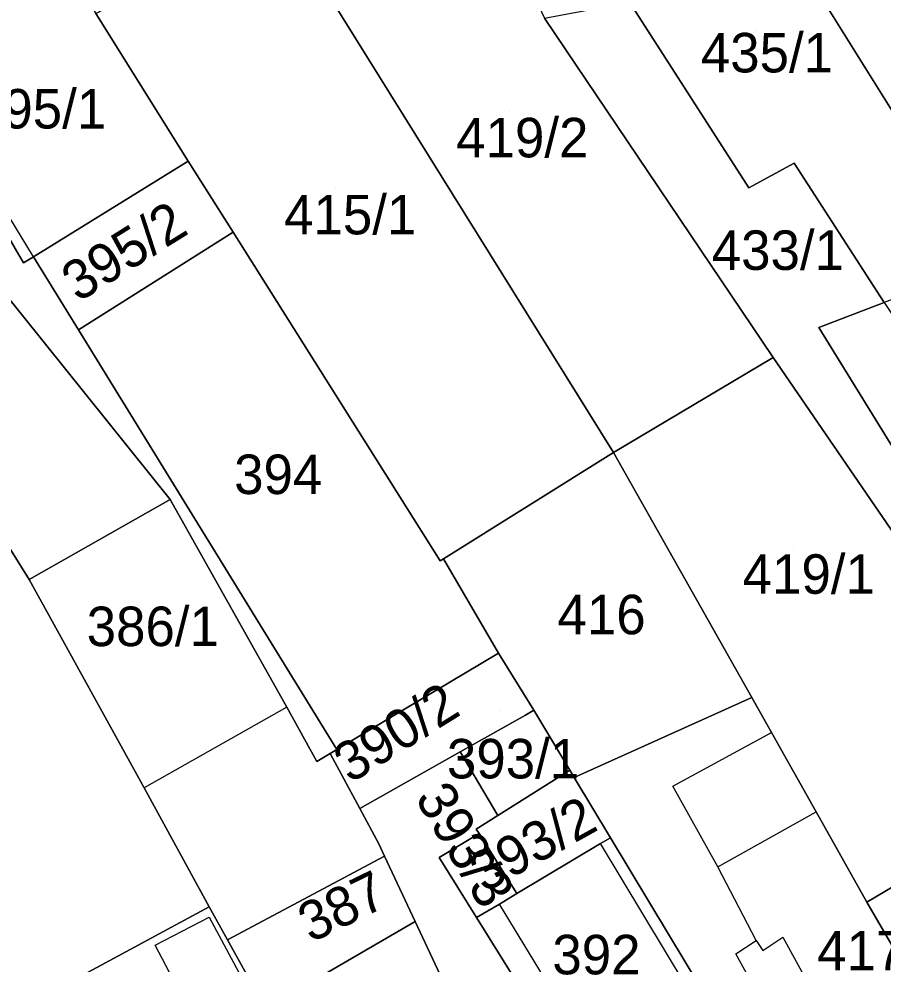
# Model space of a CAD drawing. Extents: x -263943 to -261149, y -1236934 to -1230686.
# Drawn here: x -262790.27 to -262746.54, y -1235631.56 to -1235583.7 of the extents above; entities that cross this region are included whole.
import ezdxf

# ---------------------------------------------------------------- set-up
doc = ezdxf.new("R2010")
doc.units = 0
for name, color, linetype in [('body_kn', 7, 'Continuous'), ('kladpar_druhypozemkov', 7, 'Continuous'), ('kladpar_hranice', 7, 'Continuous'), ('kladpar_parcelnecisla', 7, 'Continuous'), ('kladpar_plochy', 7, 'Continuous'), ('zappar_hrandruhpozemk', 7, 'Continuous')]:
    doc.layers.add(name, color=color, linetype=linetype)

msp = doc.modelspace()

# ---------------------------------------------------------------- linework, layer by layer
at = {"layer": 'body_kn'}
for p, q in [((-262781.7, -1235590.9), (-262781.7, -1235590.9)), ((-262781.7, -1235590.9), (-262781.7, -1235590.9)), ((-262751.05, -1235591), (-262751.05, -1235591)), ((-262753.34, -1235592.26), (-262753.34, -1235592.26)), ((-262779.43, -1235594.5), (-262779.43, -1235594.5)), ((-262790.04, -1235596.05), (-262790.04, -1235596.05)), ((-262789.53, -1235595.74), (-262789.53, -1235595.74)), ((-262789.53, -1235595.74), (-262789.53, -1235595.74)), ((-262787.25, -1235599.45), (-262787.25, -1235599.45)), ((-262749.8, -1235599.32), (-262749.8, -1235599.32)), ((-262749.8, -1235599.32), (-262749.8, -1235599.32)), ((-262752.1, -1235600.84), (-262752.1, -1235600.84)), ((-262760.19, -1235605.65), (-262760.19, -1235605.65)), ((-262782.61, -1235608.04), (-262782.61, -1235608.04)), ((-262768.95, -1235611.14), (-262768.95, -1235611.14)), ((-262768.95, -1235611.14), (-262768.95, -1235611.14)), ((-262768.79, -1235611.04), (-262768.79, -1235611.04)), ((-262789.76, -1235612.09), (-262789.76, -1235612.09)), ((-262766, -1235615.81), (-262766, -1235615.81)), ((-262753.18, -1235618.06), (-262753.18, -1235618.06)), ((-262776.72, -1235618.56), (-262776.72, -1235618.56)), ((-262776.72, -1235618.56), (-262776.72, -1235618.56)), ((-262764.64, -1235618.95), (-262764.64, -1235618.95)), ((-262764.22, -1235618.71), (-262764.22, -1235618.71)), ((-262764.22, -1235618.71), (-262764.22, -1235618.71)), ((-262752.19, -1235619.83), (-262752.19, -1235619.83)), ((-262774.53, -1235620.9), (-262774.53, -1235620.9)), ((-262774.53, -1235620.9), (-262774.53, -1235620.9)), ((-262774.19, -1235620.7), (-262774.19, -1235620.7)), ((-262774.19, -1235620.7), (-262774.19, -1235620.7)), ((-262767.95, -1235620.82), (-262767.95, -1235620.82)), ((-262767.95, -1235620.82), (-262767.95, -1235620.82)), ((-262775.19, -1235621.3), (-262775.19, -1235621.3)), ((-262762.4, -1235621.74), (-262762.4, -1235621.74)), ((-262762.17, -1235622.12), (-262762.17, -1235622.12)), ((-262783.94, -1235622.63), (-262783.94, -1235622.63)), ((-262757.19, -1235622.55), (-262757.19, -1235622.55)), ((-262773.02, -1235623.69), (-262773.02, -1235623.69)), ((-262749.93, -1235623.85), (-262749.93, -1235623.85)), ((-262766.03, -1235624.03), (-262766.03, -1235624.03)), ((-262766.03, -1235624.03), (-262766.03, -1235624.03)), ((-262767.14, -1235624.73), (-262767.14, -1235624.73)), ((-262766.99, -1235624.95), (-262766.99, -1235624.95)), ((-262760.34, -1235625.16), (-262760.34, -1235625.16)), ((-262772.06, -1235625.47), (-262772.06, -1235625.47)), ((-262767.82, -1235625.45), (-262767.82, -1235625.45)), ((-262760.84, -1235625.46), (-262760.84, -1235625.46)), ((-262771.77, -1235626.1), (-262771.77, -1235626.1)), ((-262769, -1235626.16), (-262769, -1235626.16)), ((-262754.91, -1235626.63), (-262754.91, -1235626.63)), ((-262765.07, -1235627.99), (-262765.07, -1235627.99)), ((-262765.07, -1235627.99), (-262765.07, -1235627.99)), ((-262765.95, -1235628.52), (-262765.95, -1235628.52)), ((-262747.36, -1235628.43), (-262747.36, -1235628.43)), ((-262747.36, -1235628.43), (-262747.36, -1235628.43)), ((-262780.64, -1235628.67), (-262780.64, -1235628.67)), ((-262780.64, -1235628.67), (-262780.64, -1235628.67)), ((-262780.65, -1235629.18), (-262780.65, -1235629.18)), ((-262770.22, -1235629.41), (-262770.22, -1235629.41)), ((-262767.11, -1235629.21), (-262767.11, -1235629.21)), ((-262779.72, -1235630.33), (-262779.72, -1235630.33)), ((-262779.72, -1235630.33), (-262779.72, -1235630.33)), ((-262752.97, -1235630.37), (-262752.97, -1235630.37)), ((-262752.97, -1235630.37), (-262752.97, -1235630.37)), ((-262751.61, -1235630.2), (-262751.61, -1235630.2)), ((-262783.37, -1235630.61), (-262783.37, -1235630.61)), ((-262783.37, -1235630.61), (-262783.37, -1235630.61)), ((-262753.99, -1235631.04), (-262753.99, -1235631.04)), ((-262752.63, -1235630.88), (-262752.63, -1235630.88))]:
    msp.add_line(p, q, dxfattribs=at)
at = {"layer": 'kladpar_druhypozemkov'}
for p, q in [((-262752.93, -1235584.31), (-262752.93, -1235584.31)), ((-262789.23, -1235587.18), (-262789.23, -1235587.18)), ((-262765.43, -1235588.41), (-262765.43, -1235588.41)), ((-262774.23, -1235592.26), (-262774.23, -1235592.26)), ((-262785.04, -1235594.51), (-262785.04, -1235594.51)), ((-262751.93, -1235594.46), (-262751.93, -1235594.46)), ((-262777.53, -1235605.46), (-262777.53, -1235605.46)), ((-262751.08, -1235610.56), (-262751.08, -1235610.56)), ((-262761.73, -1235612.91), (-262761.73, -1235612.91)), ((-262784.26, -1235613.39), (-262784.26, -1235613.39)), ((-262765.97, -1235618.7), (-262765.97, -1235618.7)), ((-262765.01, -1235620.87), (-262765.01, -1235620.87)), ((-262764.31, -1235624.34), (-262764.31, -1235624.34)), ((-262766.56, -1235626.45), (-262766.56, -1235626.45)), ((-262760.96, -1235629.87), (-262760.96, -1235629.87)), ((-262749.08, -1235630.06), (-262749.08, -1235630.06))]:
    msp.add_line(p, q, dxfattribs=at)
at = {"layer": 'kladpar_hranice'}
for points in [[(-262745.18, -1235587.96), (-262746.11, -1235588.3), (-262753.71, -1235576.14), (-262754.21, -1235573.25), (-262754.63, -1235572.57), (-262748.78, -1235569.02), (-262744.08, -1235577.02), (-262739.64, -1235584.59), (-262733.73, -1235593.26), (-262740.21, -1235595.7), (-262745.18, -1235587.96)], [(-262746.49, -1235598.06), (-262751.05, -1235591), (-262753.34, -1235592.26), (-262759.34, -1235582.91), (-262759.15, -1235575.95), (-262757.61, -1235574.09), (-262754.21, -1235573.25), (-262753.71, -1235576.14), (-262746.11, -1235588.3), (-262745.18, -1235587.96), (-262740.21, -1235595.7), (-262746.49, -1235598.06)], [(-262768.22, -1235574.05), (-262763.67, -1235583.66), (-262752.1, -1235600.84), (-262760.19, -1235605.65), (-262777.07, -1235578.52), (-262768.22, -1235574.05)], [(-262768.95, -1235611.14), (-262779.43, -1235594.5), (-262781.7, -1235590.9), (-262786.38, -1235583.43), (-262777.07, -1235578.52), (-262760.19, -1235605.65), (-262768.79, -1235611.04), (-262768.95, -1235611.14)], [(-262793.63, -1235581.69), (-262789.21, -1235578.92), (-262786.38, -1235583.43), (-262781.7, -1235590.9), (-262789.53, -1235595.74), (-262790.04, -1235596.05), (-262797.13, -1235583.89), (-262796.89, -1235583.74), (-262793.63, -1235581.69)], [(-262793.63, -1235581.69), (-262796.89, -1235583.74), (-262797.13, -1235583.89), (-262790.04, -1235596.05), (-262789.53, -1235595.74), (-262787.25, -1235599.45), (-262774.19, -1235620.7), (-262774.53, -1235620.9), (-262775.19, -1235621.3), (-262776.72, -1235618.56), (-262782.61, -1235608.04), (-262795.38, -1235592.13), (-262797.88, -1235587.74), (-262799.94, -1235584.13), (-262802.05, -1235579.51)], [(-262749.8, -1235599.32), (-262740.26, -1235614.79), (-262738.23, -1235617.94), (-262741.72, -1235619.97), (-262741.45, -1235616.4), (-262752.1, -1235600.84), (-262763.67, -1235583.66), (-262760.53, -1235583.07), (-262759.34, -1235582.91), (-262753.34, -1235592.26), (-262751.05, -1235591), (-262746.49, -1235598.06), (-262749.8, -1235599.32)], [(-262781.7, -1235590.9), (-262779.43, -1235594.5), (-262787.25, -1235599.45), (-262789.53, -1235595.74), (-262781.7, -1235590.9)], [(-262800.48, -1235594.66), (-262795.38, -1235592.13), (-262782.61, -1235608.04), (-262789.76, -1235612.09), (-262792.46, -1235607.75), (-262800.48, -1235594.66)], [(-262774.19, -1235620.7), (-262787.25, -1235599.45), (-262779.43, -1235594.5), (-262768.95, -1235611.14), (-262768.79, -1235611.04), (-262766, -1235615.81), (-262774.19, -1235620.7)], [(-262740.26, -1235614.79), (-262749.8, -1235599.32), (-262746.49, -1235598.06), (-262742.09, -1235604.69), (-262735.17, -1235616.51), (-262738.23, -1235617.94), (-262740.26, -1235614.79)], [(-262739.5, -1235623.78), (-262744.63, -1235626.81), (-262747.36, -1235628.43), (-262749.93, -1235623.85), (-262752.19, -1235619.83), (-262753.18, -1235618.06), (-262760.19, -1235605.65), (-262752.1, -1235600.84), (-262741.45, -1235616.4), (-262741.72, -1235619.97), (-262739.5, -1235623.78)], [(-262764.22, -1235618.71), (-262766, -1235615.81), (-262768.79, -1235611.04), (-262760.19, -1235605.65), (-262753.18, -1235618.06), (-262762.17, -1235622.12), (-262762.4, -1235621.74), (-262764.22, -1235618.71)], [(-262780.64, -1235628.67), (-262795.19, -1235636.51), (-262795.62, -1235636.77), (-262808.03, -1235616.78), (-262792.46, -1235607.75), (-262789.76, -1235612.09), (-262783.94, -1235622.63), (-262780.64, -1235628.67)], [(-262774.53, -1235620.9), (-262773.02, -1235623.69), (-262772.06, -1235625.47), (-262771.77, -1235626.1), (-262779.72, -1235630.33), (-262780.64, -1235628.67), (-262783.94, -1235622.63), (-262789.76, -1235612.09), (-262782.61, -1235608.04), (-262776.72, -1235618.56), (-262775.19, -1235621.3), (-262774.53, -1235620.9)], [(-262767.95, -1235620.82), (-262773.02, -1235623.69), (-262774.53, -1235620.9), (-262774.19, -1235620.7), (-262766, -1235615.81), (-262764.22, -1235618.71), (-262764.64, -1235618.95), (-262767.95, -1235620.82)], [(-262747.36, -1235628.43), (-262742.12, -1235637.45), (-262740.6, -1235638.98), (-262746.12, -1235641.34), (-262749.66, -1235642.87), (-262755.51, -1235633.18), (-262760.34, -1235625.16), (-262762.17, -1235622.12), (-262753.18, -1235618.06), (-262752.19, -1235619.83), (-262749.93, -1235623.85), (-262747.36, -1235628.43)], [(-262766.03, -1235624.03), (-262767.95, -1235620.82), (-262764.64, -1235618.95), (-262764.22, -1235618.71), (-262762.4, -1235621.74), (-262766.03, -1235624.03)], [(-262755.65, -1235645.46), (-262760.18, -1235647.55), (-262768.47, -1235633.15), (-262770.22, -1235629.41), (-262771.77, -1235626.1), (-262772.06, -1235625.47), (-262773.02, -1235623.69), (-262767.95, -1235620.82), (-262766.03, -1235624.03), (-262767.14, -1235624.73), (-262766.99, -1235624.95), (-262767.82, -1235625.45), (-262769, -1235626.16), (-262767.11, -1235629.21), (-262762.16, -1235637.17), (-262757.43, -1235644.78), (-262756.43, -1235644.18), (-262755.65, -1235645.46)], [(-262766.03, -1235624.03), (-262762.4, -1235621.74), (-262762.17, -1235622.12), (-262760.34, -1235625.16), (-262760.84, -1235625.46), (-262765.07, -1235627.99), (-262766.99, -1235624.95), (-262767.14, -1235624.73), (-262766.03, -1235624.03)], [(-262730.21, -1235631.37), (-262728.52, -1235633.55), (-262737.84, -1235637.74), (-262740.6, -1235638.98), (-262742.12, -1235637.45), (-262747.36, -1235628.43), (-262744.63, -1235626.81), (-262739.5, -1235623.78), (-262738.25, -1235623.04), (-262735.95, -1235621.68), (-262730.21, -1235631.37)], [(-262765.07, -1235627.99), (-262765.95, -1235628.52), (-262767.11, -1235629.21), (-262769, -1235626.16), (-262767.82, -1235625.45), (-262766.99, -1235624.95), (-262765.07, -1235627.99)], [(-262756.01, -1235633.48), (-262761.09, -1235636.53), (-262762.16, -1235637.17), (-262767.11, -1235629.21), (-262765.95, -1235628.52), (-262765.07, -1235627.99), (-262760.84, -1235625.46), (-262760.34, -1235625.16), (-262755.51, -1235633.18), (-262756.01, -1235633.48)], [(-262779.72, -1235630.33), (-262771.77, -1235626.1), (-262770.22, -1235629.41), (-262777.8, -1235633.81), (-262779.72, -1235630.33)], [(-262772.29, -1235643.8), (-262768.15, -1235650.52), (-262783.03, -1235655.9), (-262795.19, -1235636.51), (-262780.64, -1235628.67), (-262779.72, -1235630.33), (-262777.8, -1235633.81), (-262775.91, -1235637.24), (-262772.29, -1235643.8)], [(-262775.91, -1235637.24), (-262777.8, -1235633.81), (-262770.22, -1235629.41), (-262768.47, -1235633.15), (-262775.91, -1235637.24)]]:
    msp.add_lwpolyline(points, dxfattribs=at)
at = {"layer": 'kladpar_plochy'}
for points in [[(-262745.18, -1235587.96), (-262746.11, -1235588.3), (-262753.71, -1235576.14), (-262754.21, -1235573.25), (-262754.63, -1235572.57), (-262748.78, -1235569.02), (-262744.08, -1235577.02), (-262739.64, -1235584.59), (-262733.73, -1235593.26), (-262740.21, -1235595.7)], [(-262746.49, -1235598.06), (-262751.05, -1235591), (-262753.34, -1235592.26), (-262759.34, -1235582.91), (-262759.15, -1235575.95), (-262757.61, -1235574.09), (-262754.21, -1235573.25), (-262753.71, -1235576.14), (-262746.11, -1235588.3), (-262745.18, -1235587.96), (-262740.21, -1235595.7)], [(-262768.22, -1235574.05), (-262763.67, -1235583.66), (-262752.1, -1235600.84), (-262760.19, -1235605.65), (-262777.07, -1235578.52)], [(-262768.95, -1235611.14), (-262779.43, -1235594.5), (-262781.7, -1235590.9), (-262786.38, -1235583.43), (-262777.07, -1235578.52), (-262760.19, -1235605.65), (-262768.79, -1235611.04)], [(-262793.63, -1235581.69), (-262789.21, -1235578.92), (-262786.38, -1235583.43), (-262781.7, -1235590.9), (-262789.53, -1235595.74), (-262790.04, -1235596.05), (-262797.13, -1235583.89), (-262796.89, -1235583.74)], [(-262749.8, -1235599.32), (-262740.26, -1235614.79), (-262738.23, -1235617.94), (-262741.72, -1235619.97), (-262741.45, -1235616.4), (-262752.1, -1235600.84), (-262763.67, -1235583.66), (-262760.53, -1235583.07), (-262759.34, -1235582.91), (-262753.34, -1235592.26), (-262751.05, -1235591), (-262746.49, -1235598.06)], [(-262781.7, -1235590.9), (-262779.43, -1235594.5), (-262787.25, -1235599.45), (-262789.53, -1235595.74)], [(-262800.48, -1235594.66), (-262795.38, -1235592.13), (-262782.61, -1235608.04), (-262789.76, -1235612.09), (-262792.46, -1235607.75)], [(-262774.19, -1235620.7), (-262787.25, -1235599.45), (-262779.43, -1235594.5), (-262768.95, -1235611.14), (-262768.79, -1235611.04), (-262766, -1235615.81)], [(-262740.26, -1235614.79), (-262749.8, -1235599.32), (-262746.49, -1235598.06), (-262742.09, -1235604.69), (-262735.17, -1235616.51), (-262738.23, -1235617.94)], [(-262739.5, -1235623.78), (-262744.63, -1235626.81), (-262747.36, -1235628.43), (-262749.93, -1235623.85), (-262752.19, -1235619.83), (-262753.18, -1235618.06), (-262760.19, -1235605.65), (-262752.1, -1235600.84), (-262741.45, -1235616.4), (-262741.72, -1235619.97)], [(-262764.22, -1235618.71), (-262766, -1235615.81), (-262768.79, -1235611.04), (-262760.19, -1235605.65), (-262753.18, -1235618.06), (-262762.17, -1235622.12), (-262762.4, -1235621.74)], [(-262780.64, -1235628.67), (-262795.19, -1235636.51), (-262795.62, -1235636.77), (-262808.03, -1235616.78), (-262792.46, -1235607.75), (-262789.76, -1235612.09), (-262783.94, -1235622.63)], [(-262774.53, -1235620.9), (-262773.02, -1235623.69), (-262772.06, -1235625.47), (-262771.77, -1235626.1), (-262779.72, -1235630.33), (-262780.64, -1235628.67), (-262783.94, -1235622.63), (-262789.76, -1235612.09), (-262782.61, -1235608.04), (-262776.72, -1235618.56), (-262775.19, -1235621.3)], [(-262767.95, -1235620.82), (-262773.02, -1235623.69), (-262774.53, -1235620.9), (-262774.19, -1235620.7), (-262766, -1235615.81), (-262764.22, -1235618.71), (-262764.64, -1235618.95)], [(-262747.36, -1235628.43), (-262742.12, -1235637.45), (-262740.6, -1235638.98), (-262746.12, -1235641.34), (-262749.66, -1235642.87), (-262755.51, -1235633.18), (-262760.34, -1235625.16), (-262762.17, -1235622.12), (-262753.18, -1235618.06), (-262752.19, -1235619.83), (-262749.93, -1235623.85)], [(-262766.03, -1235624.03), (-262767.95, -1235620.82), (-262764.64, -1235618.95), (-262764.22, -1235618.71), (-262762.4, -1235621.74)], [(-262755.65, -1235645.46), (-262760.18, -1235647.55), (-262768.47, -1235633.15), (-262770.22, -1235629.41), (-262771.77, -1235626.1), (-262772.06, -1235625.47), (-262773.02, -1235623.69), (-262767.95, -1235620.82), (-262766.03, -1235624.03), (-262767.14, -1235624.73), (-262766.99, -1235624.95), (-262767.82, -1235625.45), (-262769, -1235626.16), (-262767.11, -1235629.21), (-262762.16, -1235637.17), (-262757.43, -1235644.78), (-262756.43, -1235644.18)], [(-262766.03, -1235624.03), (-262762.4, -1235621.74), (-262762.17, -1235622.12), (-262760.34, -1235625.16), (-262760.84, -1235625.46), (-262765.07, -1235627.99), (-262766.99, -1235624.95), (-262767.14, -1235624.73)], [(-262730.21, -1235631.37), (-262728.52, -1235633.55), (-262737.84, -1235637.74), (-262740.6, -1235638.98), (-262742.12, -1235637.45), (-262747.36, -1235628.43), (-262744.63, -1235626.81), (-262739.5, -1235623.78), (-262738.25, -1235623.04), (-262735.95, -1235621.68)], [(-262765.07, -1235627.99), (-262765.95, -1235628.52), (-262767.11, -1235629.21), (-262769, -1235626.16), (-262767.82, -1235625.45), (-262766.99, -1235624.95)], [(-262756.01, -1235633.48), (-262761.09, -1235636.53), (-262762.16, -1235637.17), (-262767.11, -1235629.21), (-262765.95, -1235628.52), (-262765.07, -1235627.99), (-262760.84, -1235625.46), (-262760.34, -1235625.16), (-262755.51, -1235633.18)], [(-262779.72, -1235630.33), (-262771.77, -1235626.1), (-262770.22, -1235629.41), (-262777.8, -1235633.81)], [(-262772.29, -1235643.8), (-262768.15, -1235650.52), (-262783.03, -1235655.9), (-262795.19, -1235636.51), (-262780.64, -1235628.67), (-262779.72, -1235630.33), (-262777.8, -1235633.81), (-262775.91, -1235637.24)], [(-262775.91, -1235637.24), (-262777.8, -1235633.81), (-262770.22, -1235629.41), (-262768.47, -1235633.15)]]:
    msp.add_lwpolyline(points, close=True, dxfattribs=at)
msp.add_lwpolyline([(-262793.63, -1235581.69), (-262796.89, -1235583.74), (-262797.13, -1235583.89), (-262790.04, -1235596.05), (-262789.53, -1235595.74), (-262787.25, -1235599.45), (-262774.19, -1235620.7), (-262774.53, -1235620.9), (-262775.19, -1235621.3), (-262776.72, -1235618.56), (-262782.61, -1235608.04), (-262795.38, -1235592.13), (-262797.88, -1235587.74), (-262799.94, -1235584.13), (-262802.05, -1235579.51)], dxfattribs=at)
at = {"layer": 'zappar_hrandruhpozemk'}
for p, q in [((-262789.53, -1235595.74), (-262796.89, -1235583.74)), ((-262776.72, -1235618.56), (-262783.94, -1235622.63)), ((-262754.91, -1235626.63), (-262749.93, -1235623.85)), ((-262756.01, -1235633.48), (-262760.84, -1235625.46)), ((-262761.09, -1235636.53), (-262765.95, -1235628.52)), ((-262751.61, -1235630.2), (-262748.99, -1235634.96)), ((-262779.99, -1235637.07), (-262783.37, -1235630.61))]:
    msp.add_line(p, q, dxfattribs=at)
for points in [[(-262754.91, -1235626.63), (-262757.19, -1235622.55), (-262752.19, -1235619.83)], [(-262749.25, -1235636.91), (-262750.44, -1235637.5), (-262753.99, -1235631.04), (-262752.97, -1235630.37), (-262754.91, -1235626.63)], [(-262783.37, -1235630.61), (-262780.65, -1235629.18), (-262777.19, -1235635.64), (-262779.99, -1235637.07)], [(-262752.97, -1235630.37), (-262752.63, -1235630.88), (-262751.61, -1235630.2)]]:
    msp.add_lwpolyline(points, dxfattribs=at)

# ---------------------------------------------------------------- texts
at = {"layer": 'kladpar_parcelnecisla'}
for s, p in [('435/1', (-262755.767, -1235586.41)), ('395/1', (-262792.547, -1235589.25)), ('419/2', (-262768.146, -1235590.71)), ('415/1', (-262776.855, -1235594.61)), ('433/1', (-262755.214, -1235596.41)), ('394', (-262779.381, -1235607.76)), ('419/1', (-262753.65, -1235612.81)), ('416', (-262763.02, -1235614.86)), ('386/1', (-262786.843, -1235615.46)), ('393/1', (-262768.614, -1235622.16)), ('392', (-262763.278, -1235632.08)), ('417', (-262749.882, -1235631.88))]:
    msp.add_text(s, height=2, dxfattribs=at).set_placement(p)
for s, rotation, p in [('395/2', 32, (-262787.272, -1235598.078)), ('390/2', 32, (-262773.502, -1235622.445)), ('393/3', 301, (-262770.266, -1235623.15)), ('393/2', 29, (-262766.723, -1235627.974)), ('387', 26, (-262775.496, -1235630.505))]:
    msp.add_text(s, height=2, rotation=rotation, dxfattribs=at).set_placement(p)

doc.saveas('drawing.dxf')
